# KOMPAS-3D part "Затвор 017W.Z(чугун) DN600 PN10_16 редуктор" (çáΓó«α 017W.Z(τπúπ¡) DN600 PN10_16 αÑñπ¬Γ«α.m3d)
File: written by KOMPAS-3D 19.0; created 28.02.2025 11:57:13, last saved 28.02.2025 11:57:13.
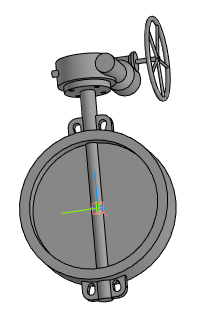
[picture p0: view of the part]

Document properties: Автор: Евгений; Полное имя файла: Затвор 017W.Z(чугун) DN600 PN10_16 редуктор.a3d

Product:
- Part/product: Затвор 017W.Z(чугун) DN600 PN10_16 редуктор
    Масса: 276.933

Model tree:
1. Операция без истории:1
